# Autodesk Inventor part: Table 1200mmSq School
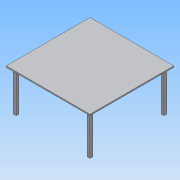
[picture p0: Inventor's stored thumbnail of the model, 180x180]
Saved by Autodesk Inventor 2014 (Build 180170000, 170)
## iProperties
Created: 2013-05
Part Number: Table 1200mmSq School
Material: Generic
Document SubType Name: Modeling
Designer: john.everitt
Mass: 31078.4 g
Surface Area: 33430.4 cm^2
Volume: 31078.4 cm^3
Density: 1 g/cm^3
Appearance: Default
Author: john.everitt
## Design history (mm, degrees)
sketch "Sketch1"
  geometry: L1 (0, 0)-(1200, 0); L2 (1200, 0)-(1200, 1200); L3 (1200, 1200)-(0, 1200); L4 (0, 1200)-(0, 0)
  constraints: 8 end point, 2 parallel, 1 horizontal, 1 perpendicular
  dimensions: "d0" = 1200 distance between parallel lines of L3 L1; "d1" = 1200 distance between parallel lines of L2 L4 (= d0)
extrude "Extrusion1" new body sketch "Sketch1" distance "d2" = 19; taper "d3" = 0 deg
sketch "Sketch2"
  geometry: L1 (-1200, 0)-(0, 0) reference; L2 (0, 0)-(0, 1200) reference; L3 (0, 1200)-(-1200, 1200) reference; L4 (-1200, 1200)-(-1200, 0) reference; L5 (-1150, 50)-(-50, 50); L6 (-50, 50)-(-50, 1150); L7 (-50, 1150)-(-1150, 1150); L8 (-1150, 1150)-(-1150, 50); L9 (-1150, 50)-(-1110, 50); L10 (-1110, 50)-(-1110, 90); L11 (-1110, 90)-(-1150, 90); L12 (-1150, 90)-(-1150, 50); L13 (-50, 50)-(-90, 50); L14 (-90, 50)-(-90, 90); L15 (-90, 90)-(-50, 90); L16 (-50, 90)-(-50, 50); L17 (-1150, 1150)-(-1110, 1150); L18 (-1110, 1150)-(-1110, 1110); L19 (-1110, 1110)-(-1150, 1110); L20 (-1150, 1110)-(-1150, 1150); L21 (-50, 1150)-(-90, 1150); L22 (-90, 1150)-(-90, 1110); L23 (-90, 1110)-(-50, 1110); L24 (-50, 1110)-(-50, 1150); 1 further point
  constraints: 40 end point, 8 parallel, 7 equal length, 4 horizontal, 4 perpendicular, 3 other
  dimensions: "d4" = 50 distance between parallel lines of L4 L8; "d5" = 40 distance between parallel lines of L10 L8
extrude "Extrusion2" join sketch "Sketch2" distance "d6" = 581; taper "d7" = 0 deg
body "Solid1"
node "Projected Loop1"
